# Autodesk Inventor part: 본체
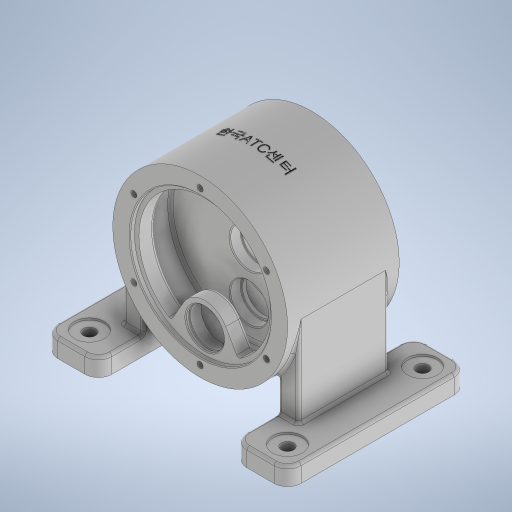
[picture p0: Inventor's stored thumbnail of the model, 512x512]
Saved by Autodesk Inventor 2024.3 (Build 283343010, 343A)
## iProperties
Created: 2025-12
Part Number: 본체
Material: 일반
Document SubType Name: Modeling
Designer: PC2-15
Density: 1 g/cm^3
Appearance: 기본값
Author: PC2-15
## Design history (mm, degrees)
sketch "스케치2"
  geometry: L1 (-135, 100)-(-75, 100); L2 (-75, 100)-(-75, -100); L3 (-75, -100)-(-135, -100); L4 (-135, -100)-(-135, 100); L5 (75, 100)-(135, 100); L6 (135, 100)-(135, -100); L7 (135, -100)-(75, -100); L8 (75, -100)-(75, 100); 2 further points
  constraints: 16 end point, 4 parallel, 2 equal length, 2 horizontal, 2 perpendicular, 1 horizontal alignment, 1 midpoint, 1 point on line
  dimensions: "d4" = 270 distance between parallel lines of L6 L4; "d5" = 135 distance from line of L4 point (0, 0) (= 0.5 x d4); "d6" = 60 distance of L5.start L5.end; "d7" = 200 distance of L5.end L6.end
extrude "돌출2" new body sketch "스케치2" distance "d8" = 20; taper "d9" = 0 deg
sketch "스케치3"
  geometry: L1 (-135, 0)-(-75, 0) reference; C1 r 97 at (0, 120); 1 further point
  constraints: 1 centre point, 1 vertical alignment
  dimensions: "d10" = 120 distance from line of L1 C1.centre; "d11" = 194 diameter of C1
extrude "돌출3" join sketch "스케치3" stored distance "d12" = 124; taper "d13" = 0 deg
sketch "스케치4"
  geometry: L1 (75, 20)-(135, 20) reference; L2 (-135, 20)-(-75, 20) reference; L3 (97, 20)-(97, 120); L4 (-97, 20)-(-97, 120); L5 (97, 120)-(75, 120); L6 (75, 120)-(75, 20); L7 (97, 20)-(75, 20); L8 (-97, 20)-(-75, 20); L9 (-75, 0)-(-75, 20) reference; L10 (-75, 20)-(-75, 120); L11 (-75, 120)-(-97, 120); A1 r 97 centre (0, 120) between (97, 120) and (-97, 120) reference; 2 further points
  constraints: 16 end point, 3 perpendicular, 3 vertical, 2 point on circle, 2 point on line, 2 tangent, 1 collinear, 1 horizontal
extrude "돌출4" join sketch "스케치4" stored distance "d14" = 100; taper "d15" = 0 deg
sketch "스케치5"
  geometry: L1 (75, 58.486)-(75, 20) reference; L2 (75, 8)-(3.735, 49.145); L3 (75, 0)-(135, 0) reference; L4 (75, 0)-(75, 20) reference; 1 further point
  constraints: 2 end point, 1 point on line
  dimensions: "d16" = 8 distance of L3.start L2.start; "d17" = 60 deg angle of L1 L2
feature "리브1" sketch "스케치5" dims "d18" = 1, "d19" = 12, "d20" = 0, "d21" = 0, "d22" = 1, "d23" = 1
sketch "스케치6"
  geometry: L1 (-62, 198)-(-57, 198); L2 (-57, 198)-(-57, 193); L3 (-57, 193)-(-40, 193); L4 (-40, 193)-(-40, 207); L5 (-40, 207)-(-8, 207); L6 (-8, 207)-(-8, 120); L7 (-8, 120)-(-62, 120); L8 (-62, 120)-(-62, 198); L9 (-62, 217)-(-62, 23) reference; L10 (62, 23)-(62, 217) reference; 3 further points
  constraints: 16 end point, 7 perpendicular, 3 midpoint, 1 horizontal
  dimensions: "d24" = 5 distance from line of L8 point (-57, 195.5); "d25" = 22 distance between parallel lines of L4 L8; "d26" = 32 distance from line of L6 point (-40, 200); "d27" = 156 diameter of L1 L7; "d28" = 146 diameter of L3 L7; "d29" = 174 diameter of L5 L7
revolve "회전1" sketch "스케치6" stored, may be unused: angle "d30" = 90 deg
sketch "스케치7"
  geometry: C1 r 87 at (0, 0) reference; 2 further points
  constraints: 1 coincident
hole "구멍1" sketch "스케치7" at (0, 0) diameter "d31" = 38; stored, may be unused: countersink angle "d35" = 90 deg, drill point angle "d37" = 118 deg; dims "d32" = 6, "d33" = 42, "d34" = 12, "d36" = 9
sketch "스케치8"
  geometry: L1 (-37.148, -62.842)-(-23.383, -39); L2 (23.383, -39)-(37.148, -62.842); L3 (0, -52.5)-(0, 0); A1 r 27 centre (0, -52.5) between (23.383, -39) and (-23.383, -39); A2 r 73 centre (0, 0) between (37.148, -62.842) and (-37.148, -62.842) reference; 1 further point
  constraints: 6 end point, 4 point on circle, 2 tangent, 1 centre point, 1 vertical, 1 vertical alignment
  dimensions: "d38" = 60 deg angle of L1 L2; "d39" = 30 deg angle of L3 L1; "d40" = 52.5 distance of L3.start L3.end; "d41" = 27 radius of A1
extrude "돌출5" join sketch "스케치8" distance "d42" = 17; taper "d43" = 0 deg
sketch "스케치9"
  geometry: L1 (-57, 88.5)-(-53.95, 88.5); L2 (-53.95, 88.5)-(-53.95, 89.75); L3 (-53.95, 89.75)-(-52, 89.75); L4 (-52, 89.75)-(-52, 88.5); L5 (-52, 88.5)-(-40, 88.5); L6 (-40, 88.5)-(-40, 67.5); L7 (-40, 67.5)-(-57, 67.5); L8 (-57, 67.5)-(-57, 88.5); L9 (-57, 94.5)-(-57, 81) reference; L10 (-57, 81)-(-57, 57.158) reference; L11 (-57, 42)-(-57, 198) reference; L12 (-57, 57.158)-(-57, 57.158) reference; L13 (-57, 57.158)-(-57, 81) reference; L14 (-57, 81)-(-57, 81) reference; L15 (-57, 81)-(-57, 57.158) reference; L16 (-50, 58.486)-(-6, 58.486) reference; L17 (-57, 81)-(-57, 81) reference; L18 (-57, 81)-(-40, 81) reference; L19 (-40, 81)-(-40, 81) reference; L20 (-57, 81)-(-40, 81) reference; L21 (-40, 57.158)-(-40, 57.158) reference; L22 (-40, 57.158)-(-40, 81) reference; L23 (-40, 81)-(-40, 81) reference; L24 (-40, 81)-(-40, 57.158) reference; L25 (-40, 33)-(-40, 207) reference; L26 (4, 99)-(-8, 99) reference; L27 (-8, 99)-(-8, 141) reference; L28 (4, 141)-(4, 99) reference; 2 further points
  constraints: 16 end point, 6 perpendicular, 4 point on line, 1 horizontal, 1 midpoint
  dimensions: "d44" = 44.5 diameter of L3 L7; "d45" = 1.95 distance between parallel lines of L2 L4; "d46" = 12 distance between parallel lines of L6 L4; "d47" = 42 diameter of L1 L7; "d108" = 52.5 distance from line of point (-8, 120) L7
revolve "회전2" sketch "스케치9" stored, may be unused: angle "d48" = 90 deg
sketch "스케치10"
  geometry: C1 r 21 at (0, -52.5) reference; 2 further points
  constraints: 1 coincident
hole "구멍2" sketch "스케치10" at (0, -52.5) diameter "d49" = 38; stored, may be unused: countersink angle "d53" = 90 deg, drill point angle "d55" = 118 deg; dims "d50" = 6, "d51" = 42, "d52" = 12, "d54" = 8
sketch "스케치11" dims "d56" = 170
  geometry: C1 r 97 at (0, 0) reference; 3 further points
  constraints: 2 vertical alignment, 3 other
hole "구멍3" sketch "스케치11" at (0, 85) diameter "d57" = 6.647; stored, may be unused: countersink angle "d61" = 90 deg, drill point angle "d63" = 118 deg; dims "d58" = 16, "d59" = 4, "d60" = 2, "d62" = 18
sketch "스케치12"
  geometry: L1 (-110, 75)-(110, 75); L2 (110, 75)-(110, -75); L3 (110, -75)-(-110, -75); L4 (-110, -75)-(-110, 75); 7 further points
  constraints: 8 end point, 4 coincident, 2 midpoint, 2 parallel, 1 horizontal, 1 horizontal alignment, 1 perpendicular, 1 vertical alignment
  dimensions: "d67" = 150 distance of L1.end L2.end; "d68" = 220 distance of L2.end L3.end
hole "구멍4" sketch "스케치12" at (-110, 75), (110, 75), (110, -75), (-110, -75) diameter "d69" = 13.5; stored, may be unused: countersink angle "d73" = 90 deg, drill point angle "d75" = 118 deg; dims "d70" = 16, "d71" = 33, "d72" = 2, "d74" = 18
fillet "모깎기1" dims "d76" = 0.6
fillet "모깎기2" dims "d77" = 3
chamfer "모따기1" distance "d78" = 1; stored, may be unused: second distance "d79" = 2, angle "d80" = 45 deg
chamfer "모따기2" distance "d81" = 1; stored, may be unused: second distance "d82" = 2, angle "d83" = 45 deg
chamfer "모따기5" distance "d90" = 1; stored, may be unused: second distance "d91" = 2, angle "d92" = 45 deg
chamfer "모따기6" distance "d93" = 1; stored, may be unused: second distance "d94" = 2, angle "d95" = 45 deg
fillet "모깎기3" dims "d96" = 3
fillet "모깎기4" dims "d97" = 3
fillet "모깎기5" dims "d98" = 15
fillet "모깎기6" dims "d99" = 3
fillet "모깎기7" dims "d100" = 3
fillet "모깎기8" dims "d101" = 3
fillet "모깎기9" dims "d102" = 3
node "작업 평면1"
sketch "스케치13"
  geometry: L1 (-38, 23)-(38, 23); L2 (38, 23)-(38, -23); L3 (38, -23)-(-38, -23); L4 (-38, -23)-(-38, 23); L5 (0, 23)-(0, -23); L6 (-38, 0)-(38, 0); 3 further points
  constraints: 6 midpoint, 4 end point, 1 coincident, 1 vertical alignment, 2 other
  dimensions: "d104" = 76 distance of L1.start L1.end; "d105" = 46 distance of L1.end L2.end
feature "엠보싱1" sketch "스케치13" dims "d106" = 0.5, "d107" = 0
chamfer "모따기7" distance "d109" = 1; stored, may be unused: second distance "d110" = 2, angle "d111" = 45 deg
fillet "모깎기10" dims "d112" = 3
fillet "모깎기11" dims "d113" = 3
node "솔리드2"
mirror "미러1"
mirror "미러2"
pattern_circular "원형 패턴1" dims angle "d65" = 360 deg
mirror "미러3"
node "투영된 루프1"
node "투영된 루프2"
node "투영된 루프3"
node "투영된 루프4"
feature "A9D066F2-1C7D-4E18-AEED-F7BC21143FA4" dims "d31" = 38, "d32" = 6, "d33" = 42, "d34" = 12, "d35" = 90 deg, "d36" = 9, "d37" = 118 deg
other parameters: "d103" = 243
